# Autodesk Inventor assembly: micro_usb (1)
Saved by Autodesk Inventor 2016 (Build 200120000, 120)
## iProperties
Created: 2016-09
Part Number: micro_usb (1)
Document SubType Name: Assembly
Designer: Administrator
Author: Administrator
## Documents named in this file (4)
- c:\worker\convert-fusion-aug-2016\tmp\job-1\19\output\files\b1646d38-3d95-4128-a552-c87d2d1b62c9\micro_usb (1).iam
- c:\worker\convert-fusion-aug-2016\tmp\job-1\19\output\files\b1646d38-3d95-4128-a552-c87d2d1b62c9\Group#12 (1).ipt
- c:\worker\convert-fusion-aug-2016\tmp\job-1\19\output\files\b1646d38-3d95-4128-a552-c87d2d1b62c9\micro_usb_plastic (1).ipt
- c:\worker\convert-fusion-aug-2016\tmp\job-1\19\output\files\b1646d38-3d95-4128-a552-c87d2d1b62c9\micro_usb_shell (1).ipt
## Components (7 placed, 3 different names)
1. Group#12 (1):1
2. Group#12 (1):2
3. Group#12 (1):3
4. Group#12 (1):4
5. Group#12 (1):5
6. micro_usb_plastic (1):1
7. micro_usb_shell (1):1
